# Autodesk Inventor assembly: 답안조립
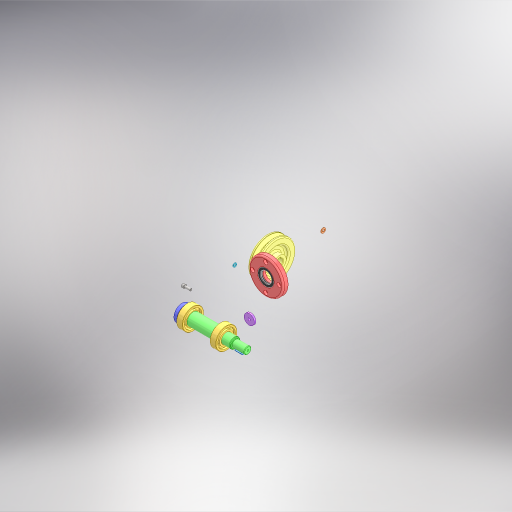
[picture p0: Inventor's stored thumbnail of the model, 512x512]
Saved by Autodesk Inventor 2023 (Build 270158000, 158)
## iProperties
Created: 2026-08
Part Number: 답안조립
Document SubType Name: Assembly
Designer: home
Author: home
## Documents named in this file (14)
- C:\Users\home\Desktop\760803V1008\답안조립.iam
- C:\Users\home\Desktop\760803V1008\본체.ipt
- C:\Users\home\Desktop\760803V1008\6각 구멍붙이 볼트 M4x12.ipt
- C:\Users\home\Desktop\760803V1008\V 벨트 풀리.ipt
- C:\Users\home\Desktop\760803V1008\깊은 홈 볼 베어링 6004.ipt
- C:\Users\home\Desktop\760803V1008\스러스트 볼 베어링 51202.ipt
- C:\Users\home\Desktop\760803V1008\스프링 와셔 M4.ipt
- C:\Users\home\Desktop\760803V1008\어댑터 슬리브.ipt
- C:\Users\home\Desktop\760803V1008\엔드 캡.ipt
- C:\Users\home\Desktop\760803V1008\오일 실 20 32 5.ipt
- C:\Users\home\Desktop\760803V1008\축.ipt
- C:\Users\home\Desktop\760803V1008\커버.ipt
- C:\Users\home\Desktop\760803V1008\평 와셔 M4.ipt
- C:\Users\home\Desktop\760803V1008\평행 키 5x5x16.ipt
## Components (2 placed, 2 different names)
1. 6각 구멍붙이 볼트 M4x12:1
2. V 벨트 풀리:1
